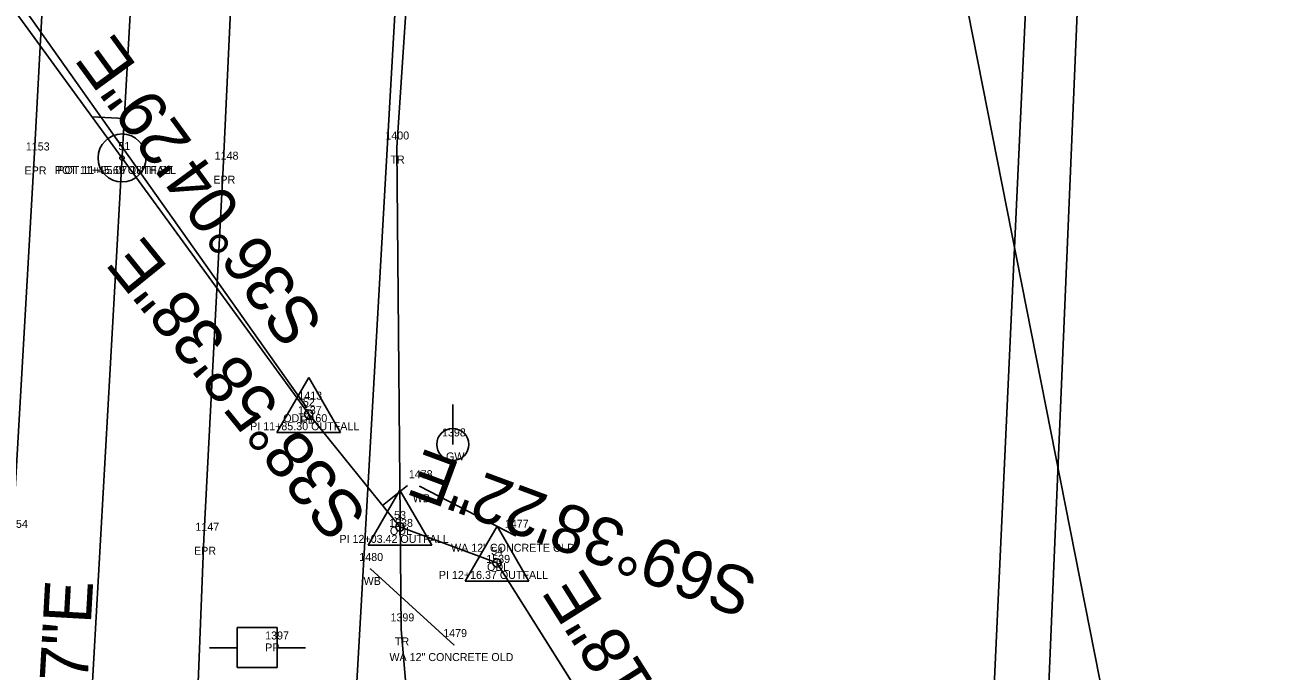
# Model space of a CAD drawing. Extents: x 1812113 to 1819860, y 1177395 to 1181185.
# Drawn here: x 1813662.4 to 1813817.4, y 1178883.7 to 1178964.5 of the extents above; entities that cross this region are included whole.
import ezdxf

# ---------------------------------------------------------------- set-up
doc = ezdxf.new("R2010")
doc.units = 0
for name, color, linetype in [('RD_EX_BldgApp', 7, 'Continuous'), ('RD_EX_BldgApp_txCode', 7, 'Continuous'), ('RD_EX_DR_Pipe', 7, 'Continuous'), ('RD_EX_DR_Pipe_txCode', 7, 'Continuous'), ('RD_EX_H2O', 7, 'Continuous'), ('RD_EX_H2O_txCode', 7, 'Continuous'), ('RD_EX_Misc', 7, 'Continuous'), ('RD_EX_Road', 7, 'Continuous'), ('RD_EX_Road_txCode', 7, 'Continuous'), ('RD_EX_RW', 7, 'Continuous'), ('RD_EX_UT', 7, 'Continuous'), ('RD_EX_UT_txCode', 7, 'Continuous'), ('RD_EX_VEG', 7, 'Continuous'), ('RD_EX_VEG_txCode', 7, 'Continuous'), ('RD_HC_CL', 7, 'Continuous'), ('RD_HC_Data', 7, 'Continuous'), ('RD_HC_Data_Tic', 7, 'Continuous'), ('RD_HC_txCode', 7, 'Continuous'), ('RD_PD_ALT1_TnTmp', 7, 'Continuous'), ('RD_SMD_Locator', 7, 'Continuous')]:
    doc.layers.add(name, color=color, linetype=linetype)

msp = doc.modelspace()

# ---------------------------------------------------------------- linework, layer by layer
at = {"layer": 'RD_EX_BldgApp'}
for p, q in [((1813723.78, 1178900.65), (1813711.77, 1178906.85)), ((1813716.08, 1178886.99), (1813705.63, 1178896.5))]:
    msp.add_line(p, q, dxfattribs=at)
at = {"layer": 'RD_EX_DR_Pipe'}
msp.add_line((1813650.55, 1178983.27), (1813697.68, 1178916.66), dxfattribs=at)
at = {"layer": 'RD_EX_H2O'}
msp.add_lwpolyline([(1813697.92, 1178915.85), (1813709.32, 1178901.76), (1813721.45, 1178897.26), (1813733.34, 1178878.37), (1813728.06, 1178852.05), (1813743.31, 1178836.1), (1813784.4, 1178814.3)], dxfattribs=at)
at = {"layer": 'RD_EX_Misc'}
for points in [[(1813405.71, 1178572.74), (1813779.17, 1178786.7), (1813799.35, 1179222.21)], [(1813408.47, 1178567.92), (1813786.33, 1178785.29), (1813804.76, 1179221.83)]]:
    msp.add_lwpolyline(points, dxfattribs=at)
at = {"layer": 'RD_EX_Road'}
for p, q in [((1813666.19, 1178996.77), (1813663.63, 1178947.81)), ((1813687.23, 1178946.66), (1813689.58, 1178995.92)), ((1813663.63, 1178947.81), (1813660.91, 1178900.64)), ((1813684.82, 1178900.28), (1813687.23, 1178946.66)), ((1813682.76, 1178849.48), (1813684.82, 1178900.28))]:
    msp.add_line(p, q, dxfattribs=at)
at = {"layer": 'RD_EX_RW'}
msp.add_line((1813698.67, 1178789.48), (1813713.48, 1179050.77), dxfattribs=at)
at = {"layer": 'RD_EX_UT'}
for p, q in [((1813715.92, 1178912.07), (1813715.92, 1178917.07)), ((1813693.98, 1178889.2), (1813688.98, 1178889.2)), ((1813688.98, 1178889.2), (1813688.98, 1178884.2)), ((1813693.98, 1178884.2), (1813693.98, 1178889.2)), ((1813685.54, 1178886.64), (1813689.01, 1178886.64)), ((1813693.9, 1178886.64), (1813697.54, 1178886.64)), ((1813688.98, 1178884.2), (1813693.98, 1178884.2))]:
    msp.add_line(p, q, dxfattribs=at)
msp.add_lwpolyline([(1813817.45, 1178777.9), (1813754.12, 1179098.9), (1813749.26, 1179176.64)], dxfattribs=at)
msp.add_circle((1813715.92, 1178912.07), 2, dxfattribs=at)
at = {"layer": 'RD_EX_VEG'}
msp.add_lwpolyline([(1813748.11, 1178842.01), (1813712.02, 1178859.16), (1813709.48, 1178888.95), (1813708.93, 1178949.18), (1813715.24, 1179043.86)], dxfattribs=at)
at = {"layer": 'RD_HC_CL'}
for p, q in [((1813663.56, 1178753.12), (1813680.53, 1179052.64)), ((1813650.05, 1178981.56), (1813697.92, 1178915.85)), ((1813697.92, 1178915.85), (1813709.32, 1178901.76)), ((1813709.32, 1178901.76), (1813721.45, 1178897.26)), ((1813721.45, 1178897.26), (1813733.34, 1178878.37))]:
    msp.add_line(p, q, dxfattribs=at)
at = {"layer": 'RD_HC_Data'}
for p, q in [((1813693.95, 1178913.56), (1813697.92, 1178920.44)), ((1813697.92, 1178920.44), (1813701.89, 1178913.56)), ((1813693.95, 1178913.56), (1813701.89, 1178913.56)), ((1813705.35, 1178899.47), (1813709.32, 1178906.35)), ((1813709.32, 1178906.35), (1813713.29, 1178899.47)), ((1813717.48, 1178894.97), (1813721.46, 1178901.85)), ((1813721.46, 1178901.85), (1813725.42, 1178894.97)), ((1813705.35, 1178899.47), (1813713.29, 1178899.47)), ((1813717.48, 1178894.97), (1813725.42, 1178894.97))]:
    msp.add_line(p, q, dxfattribs=at)
for centre, radius in [((1813674.59, 1178947.87), 3), ((1813674.59, 1178947.87), 3), ((1813674.59, 1178947.87), 0.282), ((1813674.59, 1178947.87), 0.282), ((1813697.92, 1178915.85), 0.529), ((1813709.32, 1178901.76), 0.529), ((1813721.45, 1178897.26), 0.529)]:
    msp.add_circle(centre, radius, dxfattribs=at)
at = {"layer": 'RD_HC_Data_Tic'}
for p, q in [((1813674.87, 1178952.8), (1813670.88, 1178953.02)), ((1813707.16, 1178904.43), (1813710.27, 1178906.94))]:
    msp.add_line(p, q, dxfattribs=at)
at = {"layer": 'RD_SMD_Locator'}
for centre in [(1813708.93, 1178949.18), (1813663.63, 1178947.81), (1813674.59, 1178947.87), (1813674.59, 1178947.87), (1813687.23, 1178946.66), (1813697.68, 1178916.66), (1813697.92, 1178915.85), (1813697.92, 1178915.85), (1813711.77, 1178906.85), (1813709.32, 1178901.76), (1813709.32, 1178901.76), (1813684.82, 1178900.28), (1813723.78, 1178900.65), (1813705.63, 1178896.5), (1813721.45, 1178897.26), (1813721.45, 1178897.26), (1813709.48, 1178888.95), (1813716.08, 1178886.99)]:
    msp.add_circle(centre, 0.001, dxfattribs=at)

# ---------------------------------------------------------------- texts
at = {"layer": 'RD_EX_BldgApp_txCode'}
for s, p in [('1478', (1813710.43, 1178907.85)), ('WB', (1813710.93, 1178904.85)), ('1477', (1813722.43, 1178901.65)), ('WA 12" CONCRETE OLD', (1813715.71, 1178898.65)), ('1480', (1813704.24, 1178897.5)), ('WB', (1813704.78, 1178894.5)), ('1479', (1813714.73, 1178887.99)), ('WA 12" CONCRETE OLD', (1813708.01, 1178884.99))]:
    msp.add_text(s, height=1, dxfattribs=at).set_placement(p)
at = {"layer": 'RD_EX_DR_Pipe_txCode'}
for s, p in [('1413', (1813696.62, 1178917.66)), ('PB', (1813696.9, 1178914.66))]:
    msp.add_text(s, height=1, dxfattribs=at).set_placement(p)
at = {"layer": 'RD_EX_H2O_txCode'}
for s, p in [('1537', (1813696.57, 1178915.85)), ('ODLA 60', (1813694.74, 1178914.85)), ('1538', (1813707.97, 1178901.76)), ('ODL', (1813708.07, 1178900.76)), ('1539', (1813720.11, 1178897.26)), ('ODL', (1813720.21, 1178896.26))]:
    msp.add_text(s, height=1, dxfattribs=at).set_placement(p)
at = {"layer": 'RD_EX_Road_txCode'}
for s, p in [('1153', (1813662.57, 1178948.81)), ('1148', (1813686.17, 1178947.66)), ('EPR', (1813662.41, 1178945.81)), ('EPR', (1813686, 1178944.66)), ('1154', (1813659.85, 1178901.64)), ('1147', (1813683.76, 1178901.28)), ('EPR', (1813683.59, 1178898.28))]:
    msp.add_text(s, height=1, dxfattribs=at).set_placement(p)
at = {"layer": 'RD_EX_UT_txCode'}
for s, p in [('1398', (1813714.58, 1178913.07)), ('GW', (1813715.08, 1178910.07)), ('1397', (1813692.48, 1178887.69)), ('PP', (1813692.48, 1178886.19))]:
    msp.add_text(s, height=1, dxfattribs=at).set_placement(p)
at = {"layer": 'RD_EX_VEG_txCode'}
for s, p in [('1400', (1813707.5, 1178950.18)), ('TR', (1813708.13, 1178947.18)), ('1399', (1813708.14, 1178889.95)), ('TR', (1813708.69, 1178886.95))]:
    msp.add_text(s, height=1, dxfattribs=at).set_placement(p)
at = {"layer": 'RD_HC_Data'}
for s, rotation, p in [('S32%%d11\'18"E', 122.1883, (1813756.03, 1178858.6)), ('N3%%d14\'37"E', 86.7565, (1813668.67, 1178853.93))]:
    msp.add_text(s, height=6, rotation=rotation, dxfattribs=at).set_placement(p)
at = {"layer": 'RD_HC_txCode'}
for s, p in [('31', (1813674.14, 1178948.87)), ('51', (1813674.14, 1178948.87)), ('POT 11+45.69 OUTFALL', (1813666.2, 1178945.87)), ('POT 11+95.07 13TH ST', (1813666.51, 1178945.87)), ('52', (1813697.19, 1178916.85)), ('PI 11+85.30 OUTFALL', (1813690.6, 1178913.85)), ('53', (1813708.59, 1178902.76)), ('PI 12+03.42 OUTFALL', (1813701.76, 1178899.76)), ('54', (1813720.72, 1178898.26)), ('PI 12+16.37 OUTFALL', (1813714.19, 1178895.26))]:
    msp.add_text(s, height=1, dxfattribs=at).set_placement(p)
at = {"layer": 'RD_PD_ALT1_TnTmp'}
for s, rotation, p in [('S36%%d04\'29"E', 126.0747, (1813699.95, 1178927.2)), ('S38%%d58\'38"E', 128.9771, (1813705.45, 1178903.26)), ('S69%%d38\'22"E', 159.6395, (1813754.33, 1178895.88))]:
    msp.add_text(s, height=6, rotation=rotation, dxfattribs=at).set_placement(p)

doc.saveas('drawing.dxf')
